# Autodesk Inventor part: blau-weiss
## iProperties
Created: 2004-10
Part Number: blau-weiss
Document SubType Name: Modeling
Designer: sahrens
Manufacturer: Standard
Standards Organization: Custom
Author: sahrens
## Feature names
1. Extrusion1
2. Rundung2 [Fillet]
